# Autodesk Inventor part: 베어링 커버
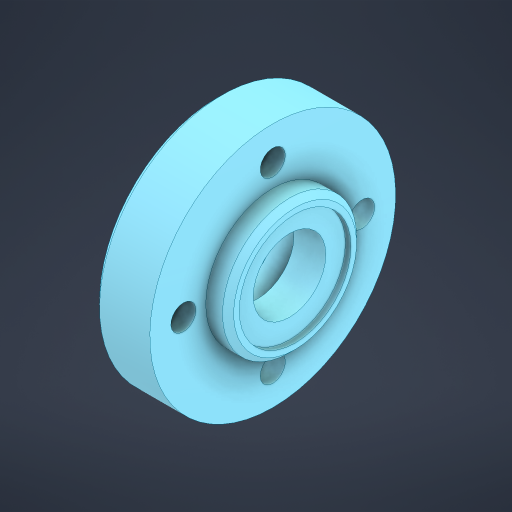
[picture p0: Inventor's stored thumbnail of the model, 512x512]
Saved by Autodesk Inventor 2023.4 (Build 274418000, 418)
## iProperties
Created: 2024-05
Part Number: 베어링 커버
Material: 강철, 연강
Document SubType Name: Modeling
Designer: Edu03
Density: 7.85 g/cm^3
Appearance: 기본값
Sending System: Autodesk Inventor 2025
Preprocessor: ST-DEVELOPER v20
Author: jhkim
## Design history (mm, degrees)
node "베어링 커버1"
node "솔리드2"
node "솔리드1"
